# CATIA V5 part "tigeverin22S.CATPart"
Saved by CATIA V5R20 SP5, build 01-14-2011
Part number: tigeverin22S
Publications: "Droite.1", "Plan.1"
Bounding box of the stored display mesh (mm): x 50 to 250, y -200 to -200, z 30 to 30
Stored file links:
  U:\think motion\fin\tigeverin22S.CATPart
  U:\think motion\fin\squelette.CATProduct
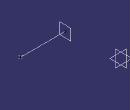
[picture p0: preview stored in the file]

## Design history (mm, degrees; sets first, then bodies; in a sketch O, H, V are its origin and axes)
External parameters (linked from other documents)
  `External.longueur tige verin2` = 200 mm
Set1
  Point1: linked copy from another document
Set2
  Line1: type PtDir, RefPoint Point1, Direction yz-plane, Start 0, End 200 {= `External.longueur tige verin2`}
  Plane1: type Normal, Curve Line1, RefPoint vertex of Line1
Body1 (main body)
